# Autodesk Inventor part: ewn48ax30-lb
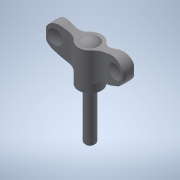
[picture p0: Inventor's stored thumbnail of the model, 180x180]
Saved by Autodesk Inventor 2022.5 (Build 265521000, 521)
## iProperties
Created: 2016-12
Part Number: ewn48ax30-lb
Material: 一般
Document SubType Name: Modeling
Designer: imaocorp
Density: 1 g/cm^3
Appearance: 既定
Author: imaocorp
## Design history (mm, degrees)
node "ewn48ax30-lb.x_t1"
node "ewn48ax30-lb"
node "Base1"
